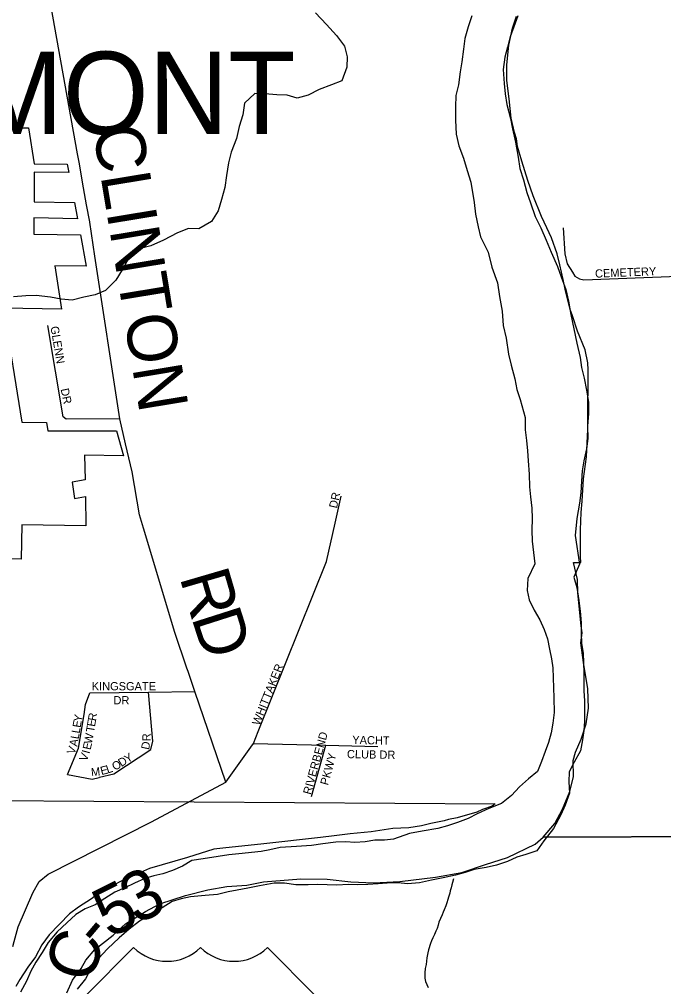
# Model space of a CAD drawing. Extents: x 1588073 to 2013523, y 1090242 to 1357120.
# Drawn here: x 1801738 to 1805645, y 1227498 to 1233367 of the extents above; entities that cross this region are included whole.
import ezdxf

# ---------------------------------------------------------------- set-up
doc = ezdxf.new("R2010")
doc.units = 0
for name, color, linetype in [('GM_X_Corporation', 7, 'Continuous'), ('GM_X_Corporation_Text', 7, 'Continuous'), ('GM_X_County_Road', 7, 'Continuous'), ('GM_X_County_Road_Text', 7, 'Continuous'), ('GM_X_Major_River', 7, 'Continuous'), ('GM_X_Minor_River', 7, 'Continuous'), ('GM_X_Section', 7, 'Continuous'), ('GM_X_Township_Subdivision', 7, 'Continuous'), ('GM_X_Township_Subdivision_Text', 7, 'Continuous'), ('GM_X_US_Shield', 7, 'Continuous')]:
    doc.layers.add(name, color=color, linetype=linetype)

msp = doc.modelspace()

# ---------------------------------------------------------------- linework, layer by layer
at = {"layer": 'GM_X_Corporation'}
msp.add_lwpolyline([(1799680, 1232744.7), (1801739.9, 1232709.3), (1801794, 1232708.4), (1801828.5, 1232491), (1802029, 1232487.8), (1802038.3, 1232437.2), (1801827.5, 1232440.7), (1801827.5, 1232260.6), (1802071.9, 1232256.1), (1802090.1, 1232156.9), (1801825.2, 1232162.1), (1801825.2, 1232064), (1802108.3, 1232059), (1802142.8, 1231868.9), (1801952.3, 1231872.6), (1801994, 1231609.7), (1801642.9, 1231615.8), (1801752.6, 1230924), (1801902.7, 1230921.4), (1801910.7, 1230871), (1802327.3, 1230870.4), (1802370, 1230719.6), (1802133.8, 1230723.7), (1802136.4, 1230573.5), (1802057.6, 1230559.6), (1802073.3, 1230460.8), (1802138.3, 1230472.3), (1802141.5, 1230294.2), (1801752.3, 1230300.9), (1801748.7, 1230092.8), (1800886.7, 1230107.6)], dxfattribs=at)
at = {"layer": 'GM_X_County_Road'}
for points in [[(1802090.5, 1232551.8), (1801902.1, 1233602.3), (1801826.4, 1234009.2), (1801770.7, 1234309.1), (1801713.5, 1234650.5), (1801537.5, 1235644.9), (1801253.4, 1237221.4), (1801246, 1237308.3), (1801251, 1237387.8), (1801278.3, 1237540.5)], [(1802099.8, 1232500.1), (1802090.5, 1232551.8)], [(1802127.6, 1232345), (1802099.8, 1232500.1)], [(1802146.2, 1232241.5), (1802127.6, 1232345)], [(1802164.7, 1232138.1), (1802146.2, 1232241.5)], [(1802196.5, 1231930.4), (1802165, 1232136.7), (1802164.7, 1232138.1)], [(1802347.2, 1230943.7), (1802196.5, 1231930.4)], [(1802382.4, 1230790.8), (1802347.2, 1230943.7)], [(1802490.3, 1230279.9), (1802465.9, 1230360.6), (1802421.4, 1230621.4), (1802382.4, 1230790.8)], [(1802754.1, 1229431.4), (1802681.2, 1229645.9), (1802490.3, 1230279.9)], [(1801698.7, 1227741.5), (1801706.8, 1227772.3), (1801730.3, 1227861.4), (1801820, 1228067.1), (1801859.2, 1228136.7), (1801912, 1228180), (1802538.5, 1228498.9), (1802989.4, 1228738.4), (1802802.7, 1229288), (1802761.1, 1229410.6), (1802754.1, 1229431.4)]]:
    msp.add_lwpolyline(points, dxfattribs=at)
at = {"layer": 'GM_X_Major_River'}
for points in [[(1804482.4, 1233389.3), (1804459.1, 1233321.4), (1804439.7, 1233251.4), (1804430.6, 1233187.3), (1804421.1, 1233109.1), (1804412, 1233048.9), (1804400.6, 1232970.8), (1804385.4, 1232904.7), (1804382.2, 1232836.4), (1804382.8, 1232756.1), (1804387.3, 1232671.6), (1804404.1, 1232598.9), (1804430.9, 1232526), (1804453.7, 1232451.2), (1804476.6, 1232380.4), (1804496.5, 1232255.4), (1804503.3, 1232185), (1804520, 1232108.3), (1804535, 1232047.7), (1804581.6, 1231954.4), (1804604.1, 1231863.5), (1804638.6, 1231768.4), (1804649.2, 1231685.8), (1804665.7, 1231597), (1804672.2, 1231510.5), (1804691, 1231433.8), (1804705.3, 1231335), (1804720.2, 1231268.4), (1804742.8, 1231185.6), (1804755.8, 1231121), (1804774.8, 1231060.3), (1804805, 1230951.2), (1804805.7, 1230876.9), (1804812.6, 1230812.4), (1804819.5, 1230750), (1804824.5, 1230687.6), (1804829.1, 1230607.1), (1804831.7, 1230530.7), (1804838.7, 1230470.2), (1804845.5, 1230401.8), (1804848.4, 1230339.4), (1804845.2, 1230267.1), (1804848, 1230200.8), (1804863.8, 1230063.2)], [(1804761.6, 1233388), (1804736.4, 1233322.2), (1804715.2, 1233262.3), (1804698, 1233198.3), (1804682.9, 1233138.3), (1804671.5, 1233062.1), (1804678, 1232977.6), (1804685, 1232915.2), (1804693.9, 1232850.7), (1804716.5, 1232765.8), (1804729.4, 1232703.3), (1804746.1, 1232622.6), (1804762.6, 1232531.8)], [(1804762.6, 1232531.8), (1804773.4, 1232463.3), (1804794.3, 1232394.5), (1804815, 1232315.8), (1804838.1, 1232255), (1804866.7, 1232172.1), (1804899.7, 1232103.1), (1804932.5, 1232028.1), (1804963.4, 1231955.2), (1805002, 1231868.1), (1805023, 1231805.4), (1805051.8, 1231728.4), (1805068.6, 1231657.8), (1805083.3, 1231577.1), (1805099.8, 1231490.4), (1805118.4, 1231401.6), (1805138.9, 1231314.8), (1805147.9, 1231254.3), (1805162.8, 1231189.7), (1805177.6, 1231117.1), (1805190.4, 1231044.5), (1805189.2, 1230976.2), (1805183.8, 1230897.9), (1805184.5, 1230823.5), (1805177.4, 1230761.3), (1805162, 1230689.3), (1805150.9, 1230627.2), (1805147.8, 1230564.9), (1805142.5, 1230494.7), (1805135.4, 1230432.5), (1805119.7, 1230338.3), (1805107.8, 1230236.1), (1805134.8, 1230061.5)], [(1804863.8, 1230063.2), (1804820.8, 1229973.5), (1804818, 1229901.4), (1804829.4, 1229845.1), (1804860.7, 1229782.6), (1804894.1, 1229724.2), (1804921.5, 1229665.7), (1804940.9, 1229607.4), (1804952.2, 1229545.1), (1804965.5, 1229486.9), (1804972.9, 1229432.7), (1804976.2, 1229372.5), (1804977.5, 1229310.4), (1804978.9, 1229250.2), (1804981.9, 1229162), (1804973.1, 1229095.9), (1804962.4, 1229037.9), (1804947.7, 1228980), (1804927.1, 1228924.1), (1804904.4, 1228864.2), (1804879.7, 1228804.3), (1804825.1, 1228758.8), (1804770.4, 1228711.3), (1804721.8, 1228657.7), (1804661.1, 1228608.2), (1804584.7, 1228578.9), (1804514.2, 1228545.6), (1804459.8, 1228518.1), (1804395.4, 1228494.8), (1804335.1, 1228473.4), (1804276.8, 1228458), (1804180.5, 1228441), (1804104.2, 1228427.7), (1804007.7, 1228392.7), (1803951.6, 1228387.3), (1803893.5, 1228385.9), (1803835.3, 1228376.5), (1803773.1, 1228373.1), (1803717.1, 1228375.8), (1803657, 1228374.4), (1803578.8, 1228365.2), (1803510.5, 1228353.9), (1803418.4, 1228348.9), (1803320.1, 1228341.9), (1803257.9, 1228328.5), (1803203.7, 1228317.1), (1803145.5, 1228311.7), (1803089.4, 1228306.3), (1803009.2, 1228297.1), (1802943, 1228287.8), (1802852.7, 1228272.7), (1802784.5, 1228263.4), (1802728, 1228228), (1802667.6, 1228202.6), (1802607.3, 1228183.2), (1802553.1, 1228169.7), (1802498.8, 1228154.2), (1802436.4, 1228126.8), (1802378, 1228097.4), (1802317.6, 1228072), (1802257.1, 1228032.6), (1802198.6, 1227995.1), (1802136.2, 1227969.7), (1802079.7, 1227936.2), (1802025.1, 1227884.7), (1801966.4, 1227831.2), (1801913.6, 1227765.6), (1801876.8, 1227705.9), (1801838.1, 1227646.2), (1801807.4, 1227592.4), (1801780.7, 1227530.5), (1801745.9, 1227464.8)], [(1805134.8, 1230061.5), (1805101.4, 1229982.5), (1805118.7, 1229920.2), (1805131.8, 1229841.9), (1805139.1, 1229775.7), (1805144.3, 1229705.5), (1805145.5, 1229641.3), (1805146.9, 1229581.2), (1805156.2, 1229520.9), (1805159.5, 1229462.8), (1805160.9, 1229404.6), (1805160.3, 1229350.5), (1805161.6, 1229292.4), (1805164.9, 1229232.2), (1805166.2, 1229168.1), (1805165.5, 1229105.9), (1805160.9, 1229051.9), (1805152.2, 1228995.8), (1805141.4, 1228927.8), (1805102.6, 1228860.1), (1805071.9, 1228802.3), (1805071.2, 1228740.1), (1805074.4, 1228671.9), (1805047.6, 1228600.1), (1805020.9, 1228540.2), (1804977.8, 1228456.5), (1804918.9, 1228383), (1804876.2, 1228321.3), (1804809.8, 1228299.9), (1804755.6, 1228284.5), (1804699.2, 1228257), (1804630.8, 1228235.7), (1804568.6, 1228220.3), (1804496.3, 1228209.1), (1804442, 1228189.6), (1804383.8, 1228174.2), (1804307.5, 1228159), (1804237.2, 1228143.7), (1804164.9, 1228128.4), (1804092.7, 1228121.2), (1804034.7, 1228127.8), (1803968.6, 1228126.5), (1803914.5, 1228121.1), (1803850.4, 1228117.8), (1803790.3, 1228116.4), (1803734.2, 1228117), (1803664, 1228113.7), (1803604, 1228116.4), (1803547.9, 1228117), (1803489.8, 1228115.6), (1803415.7, 1228116.4), (1803345.7, 1228125.2), (1803283.6, 1228125.8), (1803195.3, 1228108.7), (1803123.1, 1228095.5), (1803058.8, 1228084.1), (1803004.6, 1228072.7), (1802940.3, 1228057.3), (1802864.2, 1228050.1), (1802776, 1228043.1), (1802719.7, 1228031.6), (1802665.5, 1228014.2), (1802605, 1227976.7), (1802528.3, 1227931.4), (1802465.8, 1227896), (1802403.2, 1227846.6), (1802342.5, 1227793.1), (1802273.6, 1227727.7), (1802218.9, 1227668.2), (1802172.1, 1227608.5), (1802139.4, 1227544.7), (1802088.6, 1227483.1)]]:
    msp.add_lwpolyline(points, dxfattribs=at)
at = {"layer": 'GM_X_Minor_River'}
for points in [[(1803533.6, 1233407.4), (1803601.2, 1233336.7), (1803660.8, 1233270), (1803710.4, 1233205.3), (1803726, 1233139), (1803723.5, 1233076.8), (1803692.9, 1232994.8), (1803630.6, 1232969.2), (1803556.3, 1232941.7), (1803490, 1232908.2), (1803423.7, 1232888.7), (1803361.8, 1232907.2), (1803299.7, 1232909.8), (1803227.6, 1232916.4), (1803165.5, 1232916.9), (1803103, 1232859.2), (1803092.5, 1232787.1), (1803071.9, 1232717), (1803055.4, 1232644.9), (1803022.7, 1232560.9), (1803006.2, 1232496.8), (1802993.7, 1232420.7), (1802985.1, 1232346.5), (1802964.6, 1232274.4), (1802944, 1232206.4), (1802903.5, 1232140.5), (1802827.1, 1232097), (1802763, 1232097.5), (1802696.7, 1232072), (1802612.2, 1232026.6), (1802535.9, 1231993.1), (1802465.6, 1231975.6), (1802403.1, 1231921.9), (1802362.5, 1231848), (1802324, 1231784.1), (1802259.5, 1231722.5), (1802197.2, 1231694.9), (1802129, 1231681.4), (1802058.7, 1231663.9), (1801990.7, 1231668.5), (1801926.7, 1231681.1), (1801840.6, 1231691.8), (1801776.5, 1231690.4), (1801702.3, 1231683)], [(1804369.9, 1228152.4), (1804365.4, 1228130.5), (1804361.1, 1228116.5), (1804356.7, 1228096.6), (1804350.3, 1228078.7), (1804348.1, 1228064.7), (1804339.6, 1228040.8), (1804337.3, 1228026.9), (1804330.9, 1228007), (1804324.5, 1227989.1), (1804314, 1227963.2), (1804307.7, 1227949.3), (1804301.4, 1227933.4), (1804292.9, 1227911.6), (1804282.5, 1227889.8), (1804278.1, 1227871.8), (1804271.6, 1227849.9), (1804263.3, 1227834.1), (1804254.9, 1227814.2), (1804244.5, 1227794.4), (1804238.1, 1227776.5), (1804231.8, 1227760.6), (1804219, 1227720.8), (1804214.6, 1227702.8), (1804210, 1227672.9), (1804205.2, 1227632.9), (1804198.7, 1227609), (1804196.1, 1227581), (1804197.7, 1227562.9), (1804197.4, 1227548.9), (1804201, 1227528.8), (1804216.2, 1227492.5)]]:
    msp.add_lwpolyline(points, dxfattribs=at)
at = {"layer": 'GM_X_Section'}
for points in [[(1807054, 1228412.1), (1804914.7, 1228405.3), (1804985.2, 1228486.9), (1805031.8, 1228574.7), (1805076.5, 1228682.5), (1805099, 1228772.4), (1805095.6, 1228870.5), (1805110, 1228920.4), (1805144.5, 1229000.2), (1805175, 1229092.1), (1805189.6, 1229188.1), (1805186.3, 1229304.2), (1805159.3, 1229464.4), (1805142, 1229584.6), (1805150.4, 1229644.6), (1805144.7, 1229686.7), (1805123.9, 1229886.9), (1805122.4, 1229968.9), (1805099, 1230071.2), (1805142.4, 1230071.8), (1805140.6, 1230107.9), (1805141.6, 1230270), (1805144.3, 1230374), (1805150.7, 1230444), (1805159.6, 1230580), (1805176.4, 1230712), (1805185.4, 1230878), (1805184.5, 1231048.1), (1805186.9, 1231114.2), (1805187.7, 1231240.2), (1805185.9, 1231282.3), (1805168.4, 1231362.4), (1805123.1, 1231474.8), (1805091.7, 1231569), (1805077.9, 1231607.1), (1805050.6, 1231719.4), (1805035, 1231789.5), (1805015.5, 1231877.7), (1804999.9, 1231943.8), (1804964.5, 1232042.1), (1804936.9, 1232102.3), (1804905.3, 1232170.5), (1804854, 1232296.9), (1804820.6, 1232389.2), (1804785.3, 1232507.5), (1804759.8, 1232595.7), (1804752.1, 1232641.8), (1804740.3, 1232679.9), (1804720.9, 1232768), (1804707.6, 1232884.2), (1804694.3, 1232996.3), (1804694.8, 1233090.4), (1804705.6, 1233210.4), (1804728.3, 1233314.3), (1804752.7, 1233386.2)], [(1801580.1, 1228628), (1804623.7, 1228607.2), (1804605.6, 1228593.3), (1804547.5, 1228573.7), (1804511.3, 1228555.9), (1804393.1, 1228522.6), (1804341, 1228512.9), (1804314.9, 1228505), (1804232.8, 1228487.5), (1804176.7, 1228473.9), (1804100.6, 1228462.3), (1804002.5, 1228457), (1803872.3, 1228437.7), (1803744.1, 1228424.5), (1803648, 1228413.1), (1803563.9, 1228403.6), (1803221.5, 1228363.7), (1802971.1, 1228337.2), (1802917.1, 1228331.6), (1802758.7, 1228282.5), (1802528.1, 1228213.9), (1802363.6, 1228142.9), (1802301.4, 1228109.2), (1802239.1, 1228079.6), (1802174.8, 1228029.9), (1802096.4, 1227980.4), (1802042.2, 1227940.7), (1801919.3, 1227811.4), (1801874.9, 1227751.6), (1801836.4, 1227677.8), (1801790, 1227616.1), (1801741.5, 1227540.3), (1801717.3, 1227498.5)], [(1802025.2, 1227460.5), (1802059.7, 1227536.4), (1802112.2, 1227608.1), (1802140.5, 1227657.9), (1802194.9, 1227723.7), (1802307.5, 1227811), (1802382, 1227878.6), (1802502.5, 1227953.9), (1802590.8, 1227999.4), (1802745.2, 1228050.5), (1802881.5, 1228085.6), (1802995.7, 1228104.9), (1803117.9, 1228114.2), (1803218, 1228133.6), (1803444.3, 1228152.2), (1803604.3, 1228149.2), (1803748.3, 1228134.3), (1803886.4, 1228127.5), (1804044.5, 1228136.5), (1804260.8, 1228161.2), (1804421.1, 1228190.2), (1804565.4, 1228239.4), (1804697.8, 1228280.6), (1804866.4, 1228361.6), (1804914.7, 1228405.3), (1807054, 1228412.1)]]:
    msp.add_lwpolyline(points, dxfattribs=at)
at = {"layer": 'GM_X_Township_Subdivision'}
for points in [[(1805035.8, 1232101.9), (1805045.6, 1231944.9), (1805060.9, 1231884.3), (1805092.3, 1231833.6), (1805107.2, 1231808.2), (1805134.3, 1231793.1), (1805161.9, 1231786.3), (1805941.6, 1231817.2), (1806511.3, 1231849), (1806511.9, 1231849)], [(1802347.2, 1230943.7), (1802022.9, 1230941.6), (1802003.9, 1230956.4), (1801911.3, 1231509.1)], [(1803186.1, 1229045.7), (1803601.3, 1230077.2), (1803652.7, 1230309.8), (1803689.5, 1230474.5)], [(1802030, 1228785.8), (1802096.7, 1228945.2), (1802132, 1229149.2), (1802139, 1229209.3), (1802166.2, 1229281.1)], [(1802166.2, 1229281.1), (1802522.1, 1229284.9), (1802802.7, 1229288)], [(1802223.2, 1228768), (1802310.6, 1228789.3), (1802535.5, 1228936.2), (1802548.4, 1228988.1), (1802522.1, 1229284.9)], [(1803141.4, 1228951.6), (1803157.3, 1228974), (1803186.1, 1229045.7)], [(1803157.3, 1228974), (1803596.3, 1228962.5), (1803912.7, 1228954.3)], [(1802989.4, 1228738.4), (1803141.4, 1228951.6)], [(1803509.2, 1228651.8), (1803596.3, 1228962.5)], [(1802030, 1228785.8), (1802179.8, 1228757.4), (1802222.2, 1228767.7), (1802223.2, 1228768)]]:
    msp.add_lwpolyline(points, dxfattribs=at)
at = {"layer": 'GM_X_US_Shield'}
for p, q in [((1802430.8, 1227734.5), (1802140.7, 1227444.4)), ((1803532.9, 1227444.4), (1803242.9, 1227734.5))]:
    msp.add_line(p, q, dxfattribs=at)
for centre in [(1802633.8, 1227941.6), (1803039.8, 1227941.6)]:
    msp.add_arc(centre, 290, 225.573, 314.427, dxfattribs=at)

# ---------------------------------------------------------------- texts
at = {"layer": 'GM_X_Corporation_Text'}
msp.add_text('FREMONT', height=500, rotation=0.00001, dxfattribs=at).set_placement((1800107.9, 1232671))
at = {"layer": 'GM_X_County_Road_Text'}
for s, rotation, p in [('CLINTON', 279.36431, (1802182.7, 1232705.8)), ('R', 286.32391, (1802708.2, 1229983.6)), ('D', 287.75137, (1802779.8, 1229739.5)), ('3', 27.0124, (1802448.2, 1227871.1)), ('5', 26.81421, (1802283.6, 1227787.9)), ('-', 49.76124, (1802229.5, 1227714.2)), ('C', 73.03384, (1802173.5, 1227508.4))]:
    msp.add_text(s, height=300, rotation=rotation, dxfattribs=at).set_placement(p)
at = {"layer": 'GM_X_Township_Subdivision_Text'}
for s, rotation, p in [('CEMETERY', 2.29224, (1805230, 1231799.6)), ('GLENN', 279.65903, (1801926.5, 1231501.4)), ('DR', 281.88171, (1801988, 1231123.3)), ('DR', 77.46475, (1803663.7, 1230397.4)), ('WHITTAKER', 68.07145, (1803193.3, 1229078.9)), ('KINGSGATE', 0.00001, (1802176.8, 1229296)), ('DR', 0.00001, (1802308.8, 1229210.9)), ('Y', 80.18193, (1802115.2, 1229101.1)), ('R', 80.37687, (1802202.3, 1229107.5)), ('E', 80.19623, (1802109.2, 1229066.5)), ('E', 80.33551, (1802196.3, 1229072.7)), ('L', 80.20025, (1802097.2, 1228997.1)), ('L', 80.20087, (1802103.2, 1229031.8)), ('W', 79.66363, (1802177.9, 1228968.1)), ('T', 80.38529, (1802190.5, 1229038)), ('R', 90.66531, (1802534, 1228987.1)), ('RIVERBEND', 74.55378, (1803505.4, 1228659.9)), ('A', 78.94257, (1802088.6, 1228952.7)), ('E', 77.17985, (1802169.6, 1228931.5)), ('D', 78.4457, (1802524.1, 1228932.6)), ('YACHT', 358.80717, (1803756.6, 1228970.4)), ('V', 70.19618, (1802071.4, 1228903.3)), ('V', 68.86832, (1802145.6, 1228861.8)), ('I', 74.54564, (1802163.1, 1228907.9)), ('Y', 31.82232, (1802393.8, 1228853.2)), ('PKWY', 74.62565, (1803609.4, 1228716.5)), ('CLUB DR', 359.04564, (1803724.3, 1228884.4)), ('O', 30.86039, (1802317.8, 1228806.9)), ('D', 31.83776, (1802356.4, 1228830)), ('M', 5.50941, (1802175, 1228774.5)), ('E', 14.67189, (1802236.2, 1228781.1)), ('L', 18.18771, (1802273.4, 1228790.9))]:
    msp.add_text(s, height=50, rotation=rotation, dxfattribs=at).set_placement(p)

doc.saveas('drawing.dxf')
